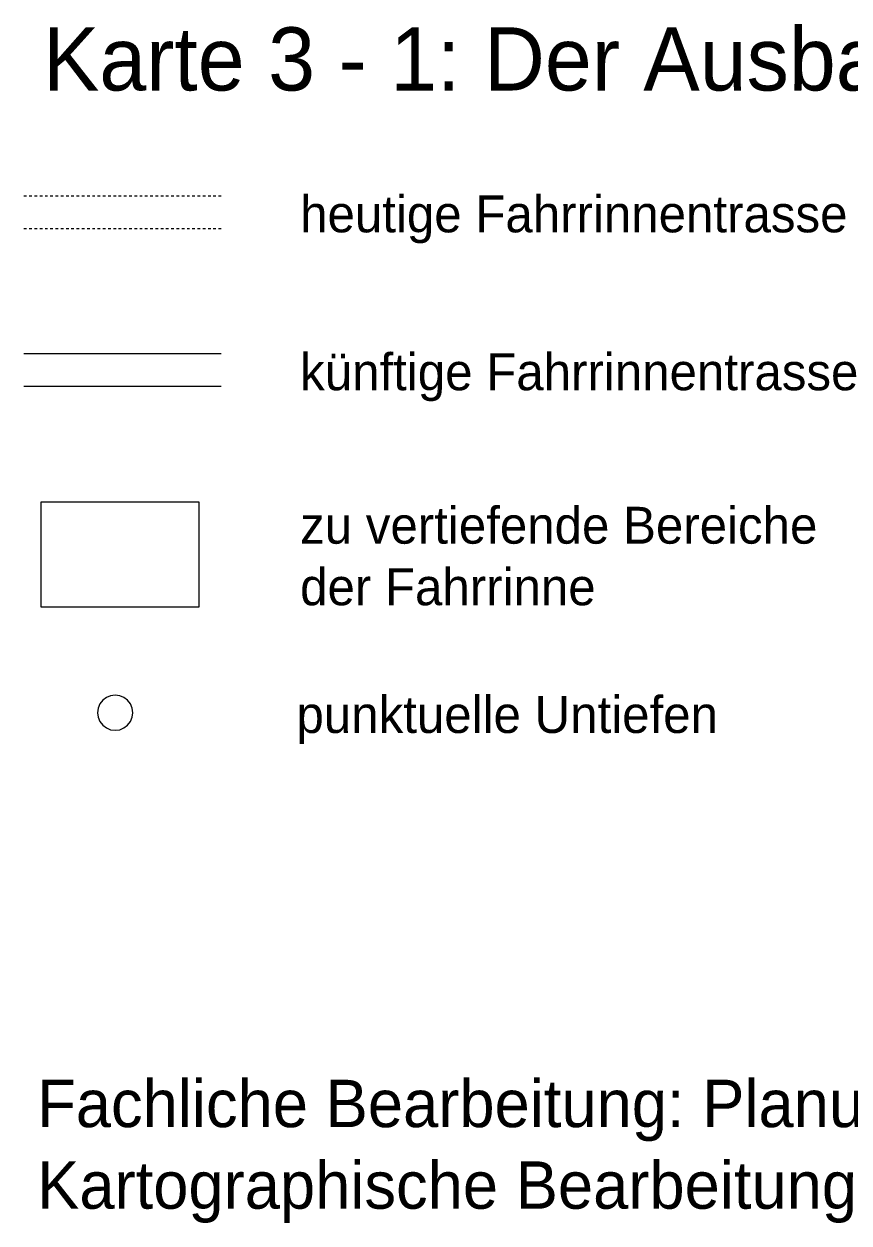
# Model space of a CAD drawing. Extents: x 3461750 to 3585707, y 5917729 to 5985917.
# Drawn here: x 3461750 to 3477436, y 5917729 to 5940508 of the extents above; entities that cross this region are included whole.
import ezdxf

# ---------------------------------------------------------------- set-up
doc = ezdxf.new("R2010")
doc.units = 0
doc.header["$LTSCALE"] = 80
doc.layers.add('16', color=7, linetype='Continuous', lineweight=13)

msp = doc.modelspace()

# ---------------------------------------------------------------- linework, layer by layer
at = {"layer": '16'}
for p, q in [((3461750, 5937244.92), (3461800, 5937244.92)), ((3461850, 5937244.92), (3461900, 5937244.92)), ((3461950, 5937244.92), (3462000, 5937244.92)), ((3462050, 5937244.92), (3462100, 5937244.92)), ((3462150, 5937244.92), (3462200, 5937244.92)), ((3462250, 5937244.92), (3462300, 5937244.92)), ((3462350, 5937244.92), (3462400, 5937244.92)), ((3462450, 5937244.92), (3462500, 5937244.92)), ((3462550, 5937244.92), (3462600, 5937244.92)), ((3462650, 5937244.92), (3462700, 5937244.92)), ((3462750, 5937244.92), (3462800, 5937244.92)), ((3462850, 5937244.92), (3462900, 5937244.92)), ((3462950, 5937244.92), (3463000, 5937244.92)), ((3463050, 5937244.92), (3463100, 5937244.92)), ((3463150, 5937244.92), (3463200, 5937244.92)), ((3463250, 5937244.92), (3463300, 5937244.92)), ((3463350, 5937244.92), (3463400, 5937244.92)), ((3463450, 5937244.92), (3463500, 5937244.92)), ((3463550, 5937244.92), (3463600, 5937244.92)), ((3463650, 5937244.92), (3463700, 5937244.92)), ((3463750, 5937244.92), (3463800, 5937244.92)), ((3463850, 5937244.92), (3463900, 5937244.92)), ((3463950, 5937244.92), (3464000, 5937244.92)), ((3464050, 5937244.92), (3464100, 5937244.92)), ((3464150, 5937244.92), (3464200, 5937244.92)), ((3464250, 5937244.92), (3464300, 5937244.92)), ((3464350, 5937244.92), (3464400, 5937244.92)), ((3464450, 5937244.92), (3464500, 5937244.92)), ((3464550, 5937244.92), (3464600, 5937244.92)), ((3464650, 5937244.92), (3464700, 5937244.92)), ((3464750, 5937244.92), (3464800, 5937244.92)), ((3464850, 5937244.92), (3464900, 5937244.92)), ((3464950, 5937244.92), (3465000, 5937244.92)), ((3465050, 5937244.92), (3465100, 5937244.92)), ((3465150, 5937244.92), (3465200, 5937244.92)), ((3465250, 5937244.92), (3465300, 5937244.92)), ((3465350, 5937244.92), (3465400, 5937244.92)), ((3465450, 5937244.92), (3465500, 5937244.92)), ((3461750, 5936619.92), (3461800, 5936619.92)), ((3461850, 5936619.92), (3461900, 5936619.92)), ((3461950, 5936619.92), (3462000, 5936619.92)), ((3462050, 5936619.92), (3462100, 5936619.92)), ((3462150, 5936619.92), (3462200, 5936619.92)), ((3462250, 5936619.92), (3462300, 5936619.92)), ((3462350, 5936619.92), (3462400, 5936619.92)), ((3462450, 5936619.92), (3462500, 5936619.92)), ((3462550, 5936619.92), (3462600, 5936619.92)), ((3462650, 5936619.92), (3462700, 5936619.92)), ((3462750, 5936619.92), (3462800, 5936619.92)), ((3462850, 5936619.92), (3462900, 5936619.92)), ((3462950, 5936619.92), (3463000, 5936619.92)), ((3463050, 5936619.92), (3463100, 5936619.92)), ((3463150, 5936619.92), (3463200, 5936619.92)), ((3463250, 5936619.92), (3463300, 5936619.92)), ((3463350, 5936619.92), (3463400, 5936619.92)), ((3463450, 5936619.92), (3463500, 5936619.92)), ((3463550, 5936619.92), (3463600, 5936619.92)), ((3463650, 5936619.92), (3463700, 5936619.92)), ((3463750, 5936619.92), (3463800, 5936619.92)), ((3463850, 5936619.92), (3463900, 5936619.92)), ((3463950, 5936619.92), (3464000, 5936619.92)), ((3464050, 5936619.92), (3464100, 5936619.92)), ((3464150, 5936619.92), (3464200, 5936619.92)), ((3464250, 5936619.92), (3464300, 5936619.92)), ((3464350, 5936619.92), (3464400, 5936619.92)), ((3464450, 5936619.92), (3464500, 5936619.92)), ((3464550, 5936619.92), (3464600, 5936619.92)), ((3464650, 5936619.92), (3464700, 5936619.92)), ((3464750, 5936619.92), (3464800, 5936619.92)), ((3464850, 5936619.92), (3464900, 5936619.92)), ((3464950, 5936619.92), (3465000, 5936619.92)), ((3465050, 5936619.92), (3465100, 5936619.92)), ((3465150, 5936619.92), (3465200, 5936619.92)), ((3465250, 5936619.92), (3465300, 5936619.92)), ((3465350, 5936619.92), (3465400, 5936619.92)), ((3465450, 5936619.92), (3465500, 5936619.92)), ((3461750, 5934250), (3465500, 5934250)), ((3461750, 5933625), (3465500, 5933625))]:
    msp.add_line(p, q, dxfattribs=at)
for points in [[(3462074.56, 5929429.39), (3462074.56, 5931429.39), (3465074.56, 5931429.39), (3465074.56, 5929429.39)], [(3463821.78, 5927421.34), (3463806.15, 5927510.01), (3463772.81, 5927590.5), (3463719.77, 5927659.62), (3463650.66, 5927712.65), (3463570.17, 5927746), (3463483.79, 5927757.37), (3463397.41, 5927746), (3463316.92, 5927712.65), (3463247.8, 5927659.62), (3463194.77, 5927590.5), (3463161.43, 5927510.01), (3463150.06, 5927423.63), (3463161.43, 5927337.26), (3463194.77, 5927256.77), (3463247.8, 5927187.65), (3463316.92, 5927134.61), (3463397.41, 5927101.27), (3463483.79, 5927089.9), (3463570.17, 5927101.27), (3463650.66, 5927134.61), (3463719.77, 5927187.65), (3463772.81, 5927256.77), (3463806.15, 5927337.26)]]:
    msp.add_lwpolyline(points, close=True, dxfattribs=at)

# ---------------------------------------------------------------- texts
for s, height, p in [('Karte 3 - 1: Der Ausbaubereich mit den Baggerbereichen und den Verbringungsstellen ', 1200, (3462111.1, 5939244.4)), ('heutige Fahrrinnentrasse', 700, (3467000, 5936550)), ('künftige Fahrrinnentrasse', 700, (3467000, 5933550)), ('zu vertiefende Bereiche', 700, (3467000, 5930635)), ('der Fahrrinne', 700, (3467000, 5929465)), ('punktuelle Untiefen', 700, (3466930.4, 5927038.7)), ('Fachliche Bearbeitung: Planungsgruppe Ökologie + Umwelt Nord', 900, (3462000, 5919550)), ('Kartographische Bearbeitung: Planungsgruppe Ökologie + Umwelt Nord', 900, (3462000, 5918000))]:
    msp.add_text(s, height=height, dxfattribs=at).set_placement(p)

doc.saveas('drawing.dxf')
